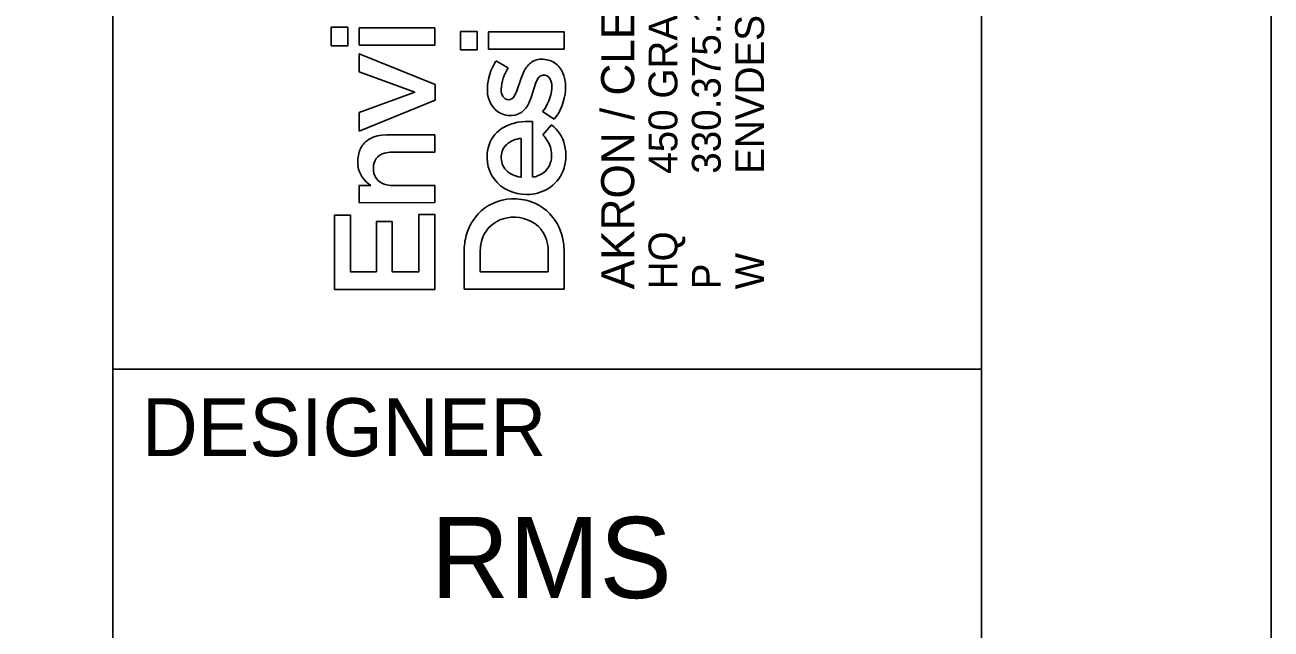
# Model space of a CAD drawing. Extents: x -0.2 to 34.2, y 0 to 22.
# Drawn here: x 32.073 to 34.225, y 2.577 to 3.62 of the extents above; entities that cross this region are included whole.
import ezdxf

# ---------------------------------------------------------------- set-up
doc = ezdxf.new("R2010")
doc.units = 0
for name, color, linetype in [('SH_Border', 7, 'Continuous'), ('SH_Cut_Line', 7, 'Continuous'), ('SH_Data', 7, 'Continuous')]:
    doc.layers.add(name, color=color, linetype=linetype)

msp = doc.modelspace()

# ---------------------------------------------------------------- linework, layer by layer
at = {"layer": 'SH_Border'}
for p, q in [((32.2249, 0.526), (32.2249, 21.526)), ((32.2249, 3.026), (33.7249, 3.026))]:
    msp.add_line(p, q, dxfattribs=at)
msp.add_lwpolyline([(1.7249, 21.526), (33.7249, 21.526), (33.7249, 0.526), (1.7249, 0.526)], close=True, dxfattribs=at)
at = {"layer": 'SH_Cut_Line'}
msp.add_lwpolyline([(0.2249, 0.026), (34.2249, 0.026), (34.2249, 22.026), (0.2249, 22.026)], close=True, dxfattribs=at)
at = {"layer": 'SH_Data'}
for p, q in [((32.602, 3.5842), (32.602, 3.6163)), ((32.602, 3.6163), (32.6304, 3.6163)), ((32.6304, 3.6163), (32.6304, 3.5842)), ((32.6504, 3.5854), (32.6504, 3.6153)), ((32.6504, 3.6153), (32.7807, 3.6153)), ((32.7807, 3.6153), (32.7807, 3.5854)), ((32.8254, 3.5771), (32.8254, 3.6092)), ((32.8254, 3.6092), (32.8538, 3.6092)), ((32.8538, 3.6092), (32.8538, 3.5771)), ((32.8738, 3.5783), (32.8738, 3.6082)), ((32.8738, 3.6082), (33.0041, 3.6082)), ((33.0041, 3.6082), (33.0041, 3.5783)), ((32.6304, 3.5842), (32.602, 3.5842)), ((32.7807, 3.5854), (32.6504, 3.5854)), ((32.8538, 3.5771), (32.8254, 3.5771)), ((33.0041, 3.5783), (32.8738, 3.5783)), ((32.6504, 3.5393), (32.6504, 3.5706)), ((32.6504, 3.5706), (32.7816, 3.5173)), ((32.8865, 3.5581), (32.9076, 3.5462)), ((32.7461, 3.504), (32.6504, 3.5393)), ((32.9298, 3.5286), (32.9353, 3.5413)), ((32.7816, 3.5173), (32.7816, 3.4904)), ((32.9217, 3.5047), (32.9298, 3.5286)), ((32.9548, 3.5193), (32.9471, 3.4948)), ((32.9584, 3.527), (32.9548, 3.5193)), ((32.6504, 3.4689), (32.7461, 3.504)), ((32.7816, 3.4904), (32.6504, 3.4368)), ((32.9179, 3.4972), (32.9217, 3.5047)), ((32.9471, 3.4948), (32.9432, 3.4852)), ((32.6504, 3.4368), (32.6504, 3.4689)), ((32.9871, 3.4574), (32.9669, 3.4707)), ((32.9495, 3.4535), (32.9496, 3.3579)), ((32.9672, 3.4306), (32.9826, 3.448)), ((32.6893, 3.43), (32.6978, 3.4304)), ((32.6978, 3.4304), (32.7806, 3.4304)), ((32.7806, 3.4304), (32.7807, 3.4006)), ((32.9298, 3.3578), (32.9298, 3.4243)), ((32.7807, 3.4006), (32.7063, 3.4006)), ((32.9285, 3.3576), (32.9298, 3.3578)), ((32.6504, 3.3135), (32.6504, 3.3433)), ((32.6504, 3.3433), (32.6705, 3.3433)), ((32.7072, 3.3433), (32.7806, 3.3433)), ((32.7806, 3.3433), (32.7807, 3.3136)), ((32.7807, 3.3136), (32.6504, 3.3135)), ((32.7535, 3.1943), (32.7535, 3.2932)), ((32.7535, 3.2932), (32.7807, 3.2932)), ((32.7807, 3.2932), (32.7807, 3.1639)), ((32.6079, 3.1639), (32.6079, 3.292)), ((32.6079, 3.292), (32.6351, 3.292)), ((32.6351, 3.292), (32.6351, 3.1943)), ((32.68, 3.1943), (32.68, 3.2809)), ((32.68, 3.2809), (32.7071, 3.2809)), ((32.7071, 3.2809), (32.7071, 3.1943)), ((32.8314, 3.164), (32.8314, 3.23)), ((32.8596, 3.2378), (32.859, 3.2283)), ((32.859, 3.2283), (32.859, 3.1944)), ((32.9764, 3.1943), (32.9765, 3.2284)), ((33.0034, 3.241), (33.0041, 3.2281)), ((33.0041, 3.2281), (33.0041, 3.164)), ((32.6351, 3.1943), (32.68, 3.1943)), ((32.7071, 3.1943), (32.7535, 3.1943)), ((32.859, 3.1944), (32.9764, 3.1943)), ((32.7807, 3.1639), (32.6079, 3.1639)), ((33.0041, 3.164), (32.8314, 3.164))]:
    msp.add_line(p, q, dxfattribs=at)
for points in [[(32.602, 3.5842), (32.602, 3.6163), (32.6304, 3.6163), (32.6304, 3.5842)], [(32.6504, 3.5854), (32.6504, 3.6153), (32.7807, 3.6153), (32.7807, 3.5854)], [(32.8254, 3.5771), (32.8254, 3.6092), (32.8538, 3.6092), (32.8538, 3.5771)], [(32.8738, 3.5783), (32.8738, 3.6082), (33.0041, 3.6082), (33.0041, 3.5783)], [(32.6504, 3.4368), (32.6504, 3.4689), (32.7461, 3.504), (32.6504, 3.5393), (32.6504, 3.5706), (32.7816, 3.5173), (32.7816, 3.4904)], [(32.6079, 3.1639), (32.6079, 3.292), (32.6351, 3.292), (32.6351, 3.1943), (32.68, 3.1943), (32.68, 3.2809), (32.7071, 3.2809), (32.7071, 3.1943), (32.7535, 3.1943), (32.7535, 3.2932), (32.7807, 3.2932), (32.7807, 3.1639)]]:
    msp.add_lwpolyline(points, close=True, dxfattribs=at)
for points in [[(32.8865, 3.5581), (32.9076, 3.5462)], [(32.9179, 3.4972), (32.9217, 3.5047), (32.9298, 3.5286), (32.9353, 3.5413)], [(32.9584, 3.527), (32.9548, 3.5193), (32.9471, 3.4948), (32.9432, 3.4852)], [(32.9871, 3.4574), (32.9669, 3.4707)], [(32.9495, 3.4535), (32.9496, 3.3579)], [(32.9672, 3.4306), (32.9826, 3.448)], [(32.6893, 3.43), (32.6978, 3.4304), (32.7806, 3.4304), (32.7807, 3.4006), (32.7063, 3.4006)], [(32.9285, 3.3576), (32.9298, 3.3578), (32.9298, 3.4243)], [(32.6504, 3.3135), (32.6504, 3.3433), (32.6705, 3.3433)], [(32.7072, 3.3433), (32.7806, 3.3433), (32.7807, 3.3136), (32.6504, 3.3135)], [(33.0034, 3.241), (33.0041, 3.2281), (33.0041, 3.164), (32.8314, 3.164)], [(32.8314, 3.164), (32.8314, 3.23)], [(32.8596, 3.2378), (32.859, 3.2283), (32.859, 3.1944), (32.9764, 3.1943), (32.9765, 3.2284)]]:
    msp.add_lwpolyline(points, dxfattribs=at)
for centre, radius, start, end in [((32.9613, 3.5086), 0.0897, 146.531, 178.7571), ((32.9613, 3.5086), 0.0897, 146.531, 178.7571), ((32.9715, 3.5231), 0.0405, 125.5118, 153.4159), ((32.9715, 3.5231), 0.0405, 125.5118, 153.4159), ((32.9655, 3.5286), 0.0326, 80.1719, 122.5197), ((32.9655, 3.5286), 0.0326, 80.1719, 122.5197), ((32.9677, 3.5242), 0.0367, 47.7934, 84.6892), ((32.9677, 3.5242), 0.0367, 47.7934, 84.6892), ((32.9628, 3.5206), 0.0427, 14.9966, 46.2063), ((32.9628, 3.5206), 0.0427, 14.9966, 46.2063), ((32.9701, 3.5049), 0.0749, 146.5112, 176.9101), ((32.9701, 3.5049), 0.0749, 146.5112, 176.9101), ((32.9688, 3.5223), 0.0114, 76.6609, 155.7053), ((32.9688, 3.5223), 0.0114, 76.6609, 155.7053), ((32.9689, 3.5211), 0.0126, 21.5098, 78.5262), ((32.9689, 3.5211), 0.0126, 21.5098, 78.5262), ((32.9354, 3.5127), 0.0712, 355.8306, 15.3914), ((32.9354, 3.5127), 0.0712, 355.8306, 15.3914), ((32.9216, 3.5084), 0.0501, 177.5366, 222.7932), ((32.9216, 3.5084), 0.0501, 177.5366, 222.7932), ((32.918, 3.5083), 0.0228, 178.4747, 211.0868), ((32.918, 3.5083), 0.0228, 178.4747, 211.0868), ((32.9074, 3.5175), 0.0757, 321.811, 354.7969), ((32.9074, 3.5175), 0.0757, 321.811, 354.7969), ((32.9509, 3.5137), 0.0321, 354.5726, 22.068), ((32.9509, 3.5137), 0.0321, 354.5726, 22.068), ((32.9083, 3.5027), 0.0115, 212.2368, 268.3777), ((32.9083, 3.5027), 0.0115, 212.2368, 268.3777), ((32.9084, 3.5019), 0.0107, 267.716, 333.7337), ((32.9084, 3.5019), 0.0107, 267.716, 333.7337), ((32.9145, 3.5142), 0.0922, 321.9777, 355.8738), ((32.9145, 3.5142), 0.0922, 321.9777, 355.8738), ((32.9109, 3.5013), 0.0375, 225.9854, 302.4797), ((32.9109, 3.5013), 0.0375, 225.9854, 302.4797), ((32.9059, 3.5018), 0.0408, 308.0877, 335.9874), ((32.9059, 3.5018), 0.0408, 308.0877, 335.9874), ((32.9273, 3.3951), 0.0558, 118.8308, 160.6244), ((32.9273, 3.3951), 0.0558, 118.8308, 160.6244), ((32.9401, 3.3701), 0.0838, 83.615, 118.2876), ((32.9401, 3.3701), 0.0838, 83.615, 118.2876), ((32.9424, 3.3977), 0.0644, 13.5336, 51.3615), ((32.9424, 3.3977), 0.0644, 13.5336, 51.3615), ((32.6936, 3.3803), 0.0499, 94.9696, 130.2225), ((32.6936, 3.3803), 0.0499, 94.9696, 130.2225), ((32.9328, 3.3821), 0.0424, 94.008, 130.8817), ((32.9328, 3.3821), 0.0424, 94.008, 130.8817), ((32.9287, 3.3915), 0.0549, 19.0357, 45.4406), ((32.9287, 3.3915), 0.0549, 19.0357, 45.4406), ((32.7037, 3.3842), 0.056, 162.2736, 187.7919), ((32.7037, 3.3842), 0.056, 162.2736, 187.7919), ((32.6884, 3.3886), 0.0402, 132.2219, 161.6818), ((32.6884, 3.3886), 0.0402, 132.2219, 161.6818), ((32.706, 3.3546), 0.046, 89.6049, 105.3284), ((32.706, 3.3546), 0.046, 89.6049, 105.3284), ((32.9354, 3.3921), 0.0644, 160.5201, 215.7831), ((32.9354, 3.3921), 0.0644, 160.5201, 215.7831), ((32.9254, 3.3923), 0.0298, 132.9851, 177.179), ((32.9254, 3.3923), 0.0298, 132.9851, 177.179), ((32.9356, 3.3957), 0.047, 344.6059, 17.007), ((32.9356, 3.3957), 0.047, 344.6059, 17.007), ((32.9313, 3.3952), 0.0758, 339.3542, 13.3785), ((32.9313, 3.3952), 0.0758, 339.3542, 13.3785), ((32.6998, 3.3747), 0.025, 103.6865, 182.2187), ((32.6998, 3.3747), 0.025, 103.6865, 182.2187), ((32.9266, 3.391), 0.0311, 175.0013, 223.283), ((32.9266, 3.391), 0.0311, 175.0013, 223.283), ((32.9473, 3.3931), 0.035, 288.0077, 343.5508), ((32.9473, 3.3931), 0.035, 288.0077, 343.5508), ((32.6952, 3.384), 0.0476, 188.962, 238.7037), ((32.6952, 3.384), 0.0476, 188.962, 238.7037), ((32.7023, 3.3716), 0.0276, 175.5854, 255.1439), ((32.7023, 3.3716), 0.0276, 175.5854, 255.1439), ((32.9339, 3.3996), 0.0423, 225.0619, 262.7974), ((32.9339, 3.3996), 0.0423, 225.0619, 262.7974), ((32.9497, 3.3781), 0.0202, 269.7003, 294.8711), ((32.9497, 3.3781), 0.0202, 269.7003, 294.8711), ((32.9439, 3.3912), 0.0626, 300.9427, 338.7323), ((32.9439, 3.3912), 0.0626, 300.9427, 338.7323), ((32.7068, 3.3855), 0.0422, 254.0916, 270.5284), ((32.7068, 3.3855), 0.0422, 254.0916, 270.5284), ((32.9375, 3.3965), 0.0687, 217.7452, 271.6543), ((32.9375, 3.3965), 0.0687, 217.7452, 271.6543), ((32.9404, 3.3984), 0.0706, 269.2048, 300.3341), ((32.9404, 3.3984), 0.0706, 269.2048, 300.3341), ((32.9172, 3.2339), 0.0864, 81.194, 125.9984), ((32.9172, 3.2339), 0.0864, 81.194, 125.9984), ((32.9195, 3.2373), 0.0827, 37.8521, 82.402), ((32.9195, 3.2373), 0.0827, 37.8521, 82.402), ((32.9188, 3.2349), 0.0865, 127.2362, 165.148), ((32.9188, 3.2349), 0.0865, 127.2362, 165.148), ((32.9139, 3.2338), 0.054, 106.1881, 157.3861), ((32.9139, 3.2338), 0.054, 106.1881, 157.3861), ((32.9177, 3.2246), 0.0639, 55.6727, 107.2093), ((32.9177, 3.2246), 0.0639, 55.6727, 107.2093), ((32.9179, 3.231), 0.0587, 357.4662, 52.2665), ((32.9179, 3.231), 0.0587, 357.4662, 52.2665), ((32.9108, 3.2317), 0.0931, 5.7333, 37.304), ((32.9108, 3.2317), 0.0931, 5.7333, 37.304), ((32.9392, 3.2288), 0.1078, 164.7861, 179.3704), ((32.9392, 3.2288), 0.1078, 164.7861, 179.3704), ((32.9232, 3.2299), 0.0641, 157.3571, 172.9275), ((32.9232, 3.2299), 0.0641, 157.3571, 172.9275)]:
    msp.add_arc(centre, radius, start, end, dxfattribs=at)

# ---------------------------------------------------------------- texts
for s, height, p in [('450 GRANT ST., AKRON, OH  44311', 0.049846, (33.1998, 3.3634)), ('AKRON / CLEVELAND / COLUMBUS', 0.056969, (33.1251, 3.164)), ('ENVDESIGNGROUP.COM', 0.049846, (33.3494, 3.3634)), ('330.375.1390', 0.049846, (33.2746, 3.3634)), ('HQ ', 0.04985, (33.1998, 3.164)), ('W', 0.0498, (33.3494, 3.164)), ('P', 0.0498, (33.2746, 3.164))]:
    msp.add_text(s, height=height, rotation=90, dxfattribs=at).set_placement(p)
for s, height, p in [('DESIGNER', 0.1, (32.2749, 2.876)), ('RMS', 0.14, (32.7741, 2.631))]:
    msp.add_text(s, height=height, dxfattribs=at).set_placement(p)

doc.saveas('drawing.dxf')
